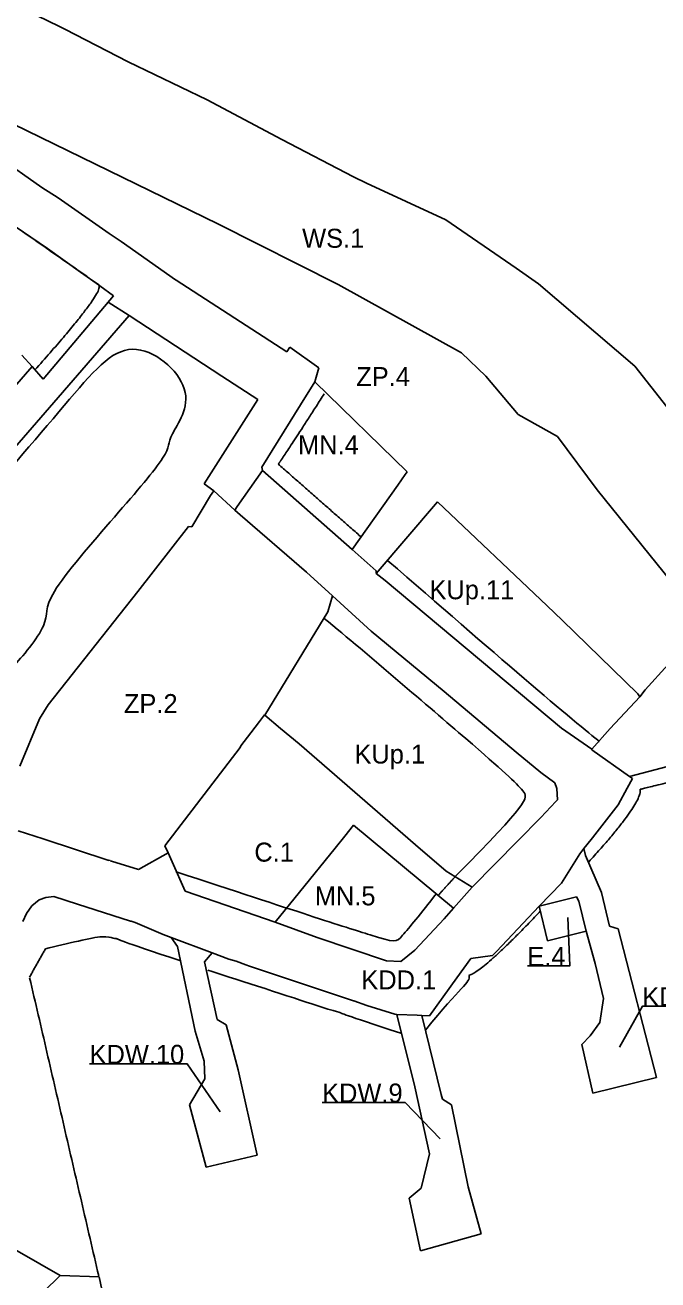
# Model space of a CAD drawing. Extents: x 7424788 to 7425732, y 5549810 to 5550591.
# Drawn here: x 7425283.7 to 7425416.8, y 5550184.4 to 5550448.5 of the extents above; entities that cross this region are included whole.
import ezdxf

# ---------------------------------------------------------------- set-up
doc = ezdxf.new("R2010")
doc.units = 0
for name, color, linetype in [('WIL_granica obszaru objętego planem', 7, 'Continuous'), ('WIL_linia rozgraniczające tereny o różnym przeznaczeniu lub różnych zasadach zagospodarowania', 7, 'Continuous'), ('WIL_linia rozgraniczające tereny o różnym przeznaczeniu lub różnych zasadach zagospodarowania_OPISY', 7, 'Continuous'), ('WIL_nieprzekraczalne linie zabudowy', 7, 'Continuous')]:
    doc.layers.add(name, color=color, linetype=linetype)

msp = doc.modelspace()

# ---------------------------------------------------------------- linework, layer by layer
at = {"layer": 'WIL_granica obszaru objętego planem'}
for p, q in [((7425283.84, 5550451.64), (7425290.93, 5550448.2)), ((7425290.93, 5550448.2), (7425292.05, 5550447.63)), ((7425292.05, 5550447.63), (7425305.36, 5550440.81)), ((7425305.36, 5550440.81), (7425321.99, 5550432.8)), ((7425321.99, 5550432.8), (7425337.74, 5550424.46)), ((7425337.74, 5550424.46), (7425352.81, 5550416.55)), ((7425352.81, 5550416.55), (7425355.56, 5550415.28)), ((7425355.56, 5550415.28), (7425372.22, 5550407.56)), ((7425372.22, 5550407.56), (7425386.99, 5550397.33)), ((7425386.99, 5550397.33), (7425391.75, 5550394.04)), ((7425391.75, 5550394.04), (7425411.96, 5550376.76)), ((7425411.96, 5550376.76), (7425426.3, 5550358.5))]:
    msp.add_line(p, q, dxfattribs=at)
at = {"layer": 'WIL_linia rozgraniczające tereny o różnym przeznaczeniu lub różnych zasadach zagospodarowania'}
for p, q in [((7425283.84, 5550451.64), (7425290.93, 5550448.2)), ((7425290.93, 5550448.2), (7425292.05, 5550447.63)), ((7425292.05, 5550447.63), (7425305.36, 5550440.81)), ((7425305.36, 5550440.81), (7425321.99, 5550432.8)), ((7425321.99, 5550432.8), (7425337.74, 5550424.46)), ((7425278.31, 5550429.04), (7425324.29, 5550406.7)), ((7425337.74, 5550424.46), (7425352.81, 5550416.55)), ((7425287.26, 5550414.34), (7425277.85, 5550420.91)), ((7425352.81, 5550416.55), (7425355.56, 5550415.28)), ((7425290.7, 5550412.16), (7425287.26, 5550414.34)), ((7425355.56, 5550415.28), (7425372.22, 5550407.56)), ((7425301.42, 5550404.68), (7425290.7, 5550412.16)), ((7425288.42, 5550401.48), (7425281.41, 5550406.3)), ((7425324.29, 5550406.7), (7425349.6, 5550393.9)), ((7425372.22, 5550407.56), (7425386.99, 5550397.33)), ((7425303.95, 5550403), (7425301.42, 5550404.68)), ((7425295.4, 5550396.55), (7425288.42, 5550401.48)), ((7425315.38, 5550394.87), (7425303.95, 5550403)), ((7425299.38, 5550393.69), (7425295.4, 5550396.55)), ((7425386.99, 5550397.33), (7425391.75, 5550394.04)), ((7425299.43, 5550393.65), (7425299.38, 5550393.69)), ((7425302.31, 5550391.51), (7425299.43, 5550393.65)), ((7425315.49, 5550394.8), (7425315.38, 5550394.87)), ((7425338.75, 5550379.76), (7425315.49, 5550394.8)), ((7425349.6, 5550393.9), (7425375.52, 5550379.54)), ((7425391.75, 5550394.04), (7425411.96, 5550376.76)), ((7425287.5, 5550374.02), (7425302.31, 5550391.51)), ((7425305.59, 5550387.37), (7425301.21, 5550390.22)), ((7425288.84, 5550368.05), (7425304.66, 5550386.33)), ((7425304.66, 5550386.33), (7425305.59, 5550387.37)), ((7425305.59, 5550387.37), (7425325.13, 5550374.65)), ((7425339.41, 5550380.73), (7425338.75, 5550379.76)), ((7425345.52, 5550376.4), (7425339.41, 5550380.73)), ((7425283, 5550379.03), (7425285.18, 5550376.64)), ((7425375.52, 5550379.54), (7425380.62, 5550374.6)), ((7425285.18, 5550376.64), (7425260.42, 5550348.39)), ((7425285.18, 5550376.64), (7425287.5, 5550374.02)), ((7425325.13, 5550374.65), (7425332.65, 5550369.75)), ((7425344.66, 5550373.45), (7425345.52, 5550376.4)), ((7425380.62, 5550374.6), (7425387.41, 5550366.58)), ((7425411.96, 5550376.76), (7425426.3, 5550358.5)), ((7425341.63, 5550368.63), (7425344.66, 5550373.45)), ((7425344.66, 5550373.45), (7425364.09, 5550354.52)), ((7425332.65, 5550369.75), (7425321.37, 5550351.99)), ((7425281.55, 5550359.6), (7425288.84, 5550368.05)), ((7425333.48, 5550355.5), (7425341.63, 5550368.63)), ((7425387.41, 5550366.58), (7425395.74, 5550361.95)), ((7425395.74, 5550361.95), (7425404.07, 5550350.68)), ((7425328.34, 5550347.21), (7425333.62, 5550354.76)), ((7425333.62, 5550354.76), (7425333.48, 5550355.5)), ((7425352.5, 5550338.18), (7425333.62, 5550354.76)), ((7425363.66, 5550353.95), (7425362.1, 5550351.69)), ((7425364.09, 5550354.52), (7425363.66, 5550353.95)), ((7425321.37, 5550351.99), (7425323.45, 5550350.51)), ((7425362.1, 5550351.69), (7425352.5, 5550338.18)), ((7425404.07, 5550350.68), (7425423.19, 5550326.93)), ((7425322.74, 5550349.49), (7425318.82, 5550342.91)), ((7425323.45, 5550350.51), (7425322.74, 5550349.49)), ((7425327.86, 5550346.44), (7425323.45, 5550350.51)), ((7425357.57, 5550333.12), (7425370.48, 5550348.19)), ((7425370.48, 5550348.19), (7425393.54, 5550326.29)), ((7425327.86, 5550346.44), (7425328.34, 5550347.21)), ((7425328.96, 5550345.48), (7425327.86, 5550346.44)), ((7425342.88, 5550333.36), (7425328.96, 5550345.48)), ((7425318.09, 5550342.99), (7425307.41, 5550329.28)), ((7425318.82, 5550342.91), (7425318.09, 5550342.99)), ((7425357.54, 5550333.65), (7425352.5, 5550338.18)), ((7425348.37, 5550328.37), (7425342.88, 5550333.36)), ((7425357.57, 5550333.12), (7425357.54, 5550333.65)), ((7425357.58, 5550333.07), (7425357.57, 5550333.12)), ((7425359.48, 5550331.6), (7425357.58, 5550333.07)), ((7425396.53, 5550300.55), (7425359.48, 5550331.6)), ((7425307.41, 5550329.28), (7425288.58, 5550305.46)), ((7425347.4, 5550325.01), (7425348.37, 5550328.37)), ((7425348.37, 5550328.37), (7425356.49, 5550320.98)), ((7425334.14, 5550303.26), (7425347.4, 5550325.01)), ((7425393.54, 5550326.29), (7425396.71, 5550323.28)), ((7425396.71, 5550323.28), (7425412.64, 5550307.77)), ((7425356.49, 5550320.98), (7425371.86, 5550308.29)), ((7425419.02, 5550313.96), (7425414.16, 5550308.65)), ((7425371.86, 5550308.29), (7425387.02, 5550295.51)), ((7425414.16, 5550308.65), (7425413.01, 5550307.15)), ((7425413.01, 5550307.15), (7425406.81, 5550300.45)), ((7425412.64, 5550307.77), (7425413.01, 5550307.15)), ((7425288.58, 5550305.46), (7425286.73, 5550302.51)), ((7425333.01, 5550301.92), (7425334.07, 5550303.32)), ((7425334.07, 5550303.32), (7425334.14, 5550303.26)), ((7425334.14, 5550303.26), (7425337.46, 5550300.5)), ((7425286.73, 5550302.51), (7425282.57, 5550292.54)), ((7425331.21, 5550299.55), (7425333.01, 5550301.92)), ((7425337.46, 5550300.5), (7425341.38, 5550297.24)), ((7425402.95, 5550296.13), (7425396.53, 5550300.55)), ((7425406.81, 5550300.45), (7425402.95, 5550296.13)), ((7425329.12, 5550296.8), (7425331.21, 5550299.55)), ((7425313.1, 5550275.8), (7425328.96, 5550296.5)), ((7425328.96, 5550296.5), (7425329.12, 5550296.8)), ((7425341.38, 5550297.24), (7425365.86, 5550275.99)), ((7425387.02, 5550295.51), (7425392.21, 5550291.24)), ((7425402.95, 5550296.13), (7425402.92, 5550296.01)), ((7425402.92, 5550296.01), (7425410.83, 5550290.4)), ((7425410.83, 5550290.4), (7425431.76, 5550295.88)), ((7425392.21, 5550291.24), (7425395.14, 5550289.05)), ((7425411.46, 5550289.96), (7425410.36, 5550287.92)), ((7425410.83, 5550290.4), (7425411.46, 5550289.96)), ((7425395.14, 5550289.05), (7425395.6, 5550287.88)), ((7425395.6, 5550287.88), (7425395.72, 5550285.49)), ((7425410.36, 5550287.92), (7425408.49, 5550284.43)), ((7425395.34, 5550285.09), (7425392.19, 5550281.76)), ((7425395.72, 5550285.49), (7425395.34, 5550285.09)), ((7425408.49, 5550284.43), (7425403.07, 5550277.5)), ((7425350.96, 5550277.84), (7425352.8, 5550280.12)), ((7425352.8, 5550280.12), (7425373.84, 5550262.67)), ((7425392.19, 5550281.76), (7425387.38, 5550276.86)), ((7425282.27, 5550278.94), (7425287.49, 5550277.24)), ((7425287.49, 5550277.24), (7425301.33, 5550272.71)), ((7425348.91, 5550275.3), (7425350.96, 5550277.84)), ((7425387.38, 5550276.86), (7425377.77, 5550267.07)), ((7425402.78, 5550277.13), (7425401.28, 5550275.21)), ((7425403.07, 5550277.5), (7425402.78, 5550277.13)), ((7425307.56, 5550270.77), (7425313.79, 5550274.34)), ((7425313.79, 5550274.34), (7425313.1, 5550275.8)), ((7425314.64, 5550272.44), (7425313.79, 5550274.34)), ((7425341.44, 5550266.03), (7425348.91, 5550275.3)), ((7425365.86, 5550275.99), (7425372.28, 5550270.42)), ((7425396.55, 5550267.91), (7425400.41, 5550274.09)), ((7425400.41, 5550274.09), (7425401.28, 5550275.21)), ((7425401.28, 5550275.21), (7425401.61, 5550273.78)), ((7425301.33, 5550272.71), (7425301.36, 5550272.8)), ((7425301.36, 5550272.8), (7425301.62, 5550272.71)), ((7425301.62, 5550272.71), (7425301.6, 5550272.62)), ((7425301.6, 5550272.62), (7425301.9, 5550272.53)), ((7425301.9, 5550272.53), (7425307.56, 5550270.77)), ((7425317.39, 5550266.24), (7425314.64, 5550272.44)), ((7425401.61, 5550273.78), (7425404.96, 5550265.94)), ((7425372.28, 5550270.42), (7425377.77, 5550267.07)), ((7425336.32, 5550259.75), (7425317.39, 5550266.24)), ((7425336.32, 5550259.75), (7425341.44, 5550266.03)), ((7425377.77, 5550267.07), (7425373.84, 5550262.67)), ((7425391.89, 5550263.11), (7425396.54, 5550267.9)), ((7425396.54, 5550267.9), (7425396.55, 5550267.91)), ((7425286.66, 5550264.41), (7425285.11, 5550263.16)), ((7425288.06, 5550264.92), (7425286.66, 5550264.41)), ((7425289.72, 5550265.09), (7425288.06, 5550264.92)), ((7425294.74, 5550263.5), (7425289.72, 5550265.09)), ((7425305.86, 5550259.95), (7425294.74, 5550263.5)), ((7425391.89, 5550263.11), (7425399.72, 5550265.03)), ((7425399.72, 5550265.03), (7425400.19, 5550264.15)), ((7425400.19, 5550264.15), (7425401.78, 5550257.83)), ((7425404.96, 5550265.94), (7425406.65, 5550258.85)), ((7425283.97, 5550261.56), (7425283.22, 5550259.84)), ((7425285.11, 5550263.16), (7425283.97, 5550261.56)), ((7425373.84, 5550262.67), (7425371.84, 5550260.44)), ((7425391.89, 5550263.11), (7425382.87, 5550253.57)), ((7425393.61, 5550255.77), (7425391.89, 5550263.11)), ((7425306, 5550259.91), (7425305.86, 5550259.95)), ((7425306.84, 5550259.64), (7425306, 5550259.91)), ((7425312.76, 5550257.14), (7425306.84, 5550259.64)), ((7425345.18, 5550256.52), (7425336.32, 5550259.75)), ((7425371.84, 5550260.44), (7425365.7, 5550253.86)), ((7425406.65, 5550258.85), (7425408.45, 5550258.32)), ((7425408.45, 5550258.32), (7425416.57, 5550227.04)), ((7425314.41, 5550256.52), (7425312.76, 5550257.14)), ((7425314.41, 5550256.52), (7425323.03, 5550253.26)), ((7425315.78, 5550254.6), (7425314.41, 5550256.52)), ((7425359.73, 5550251.59), (7425345.18, 5550256.52)), ((7425401.78, 5550257.83), (7425393.61, 5550255.77)), ((7425403.65, 5550251), (7425401.78, 5550257.83)), ((7425319.51, 5550236.75), (7425315.78, 5550254.6)), ((7425323.03, 5550253.26), (7425321.47, 5550251.38)), ((7425326.55, 5550251.93), (7425323.03, 5550253.26)), ((7425365.7, 5550253.86), (7425362.79, 5550251.43)), ((7425382.87, 5550253.57), (7425382.05, 5550252.7)), ((7425321.47, 5550251.38), (7425324.1, 5550239.21)), ((7425328.08, 5550251.49), (7425326.55, 5550251.93)), ((7425330.12, 5550250.76), (7425328.08, 5550251.49)), ((7425330.92, 5550250.48), (7425330.12, 5550250.76)), ((7425352.79, 5550243.19), (7425330.92, 5550250.48)), ((7425362.79, 5550251.43), (7425359.73, 5550251.59)), ((7425377.47, 5550252.05), (7425374.55, 5550248.01)), ((7425382.05, 5550252.7), (7425377.47, 5550252.05)), ((7425405.39, 5550243.68), (7425403.65, 5550251)), ((7425374.55, 5550248.01), (7425368.78, 5550240.03)), ((7425352.86, 5550243.17), (7425352.79, 5550243.19)), ((7425355.63, 5550242.21), (7425352.86, 5550243.17)), ((7425404.59, 5550238.62), (7425405.39, 5550243.68)), ((7425361.46, 5550240.33), (7425355.63, 5550242.21)), ((7425361.92, 5550240.31), (7425361.46, 5550240.33)), ((7425365.71, 5550225.04), (7425361.92, 5550240.31)), ((7425361.92, 5550240.31), (7425366.17, 5550240.14)), ((7425366.17, 5550240.14), (7425367.19, 5550240.1)), ((7425367.19, 5550240.1), (7425371.22, 5550223.44)), ((7425368.78, 5550240.03), (7425367.19, 5550240.1)), ((7425324.1, 5550239.21), (7425326.04, 5550238.09)), ((7425326.04, 5550238.09), (7425328.56, 5550228.63)), ((7425402.59, 5550235.82), (7425404.59, 5550238.62)), ((7425321.38, 5550230.5), (7425319.51, 5550236.75)), ((7425400.86, 5550233.96), (7425402.59, 5550235.82)), ((7425403.12, 5550223.71), (7425400.86, 5550233.96)), ((7425321.51, 5550226.77), (7425321.38, 5550230.5)), ((7425318.31, 5550221.31), (7425321.51, 5550226.77)), ((7425328.56, 5550228.63), (7425332.56, 5550210.66)), ((7425416.57, 5550227.04), (7425403.12, 5550223.71)), ((7425368.77, 5550210.93), (7425365.71, 5550225.04)), ((7425321.77, 5550208.13), (7425318.31, 5550221.31)), ((7425371.22, 5550223.44), (7425371.5, 5550222.48)), ((7425371.5, 5550222.48), (7425373.43, 5550221.31)), ((7425373.43, 5550221.31), (7425376.89, 5550204)), ((7425332.56, 5550210.66), (7425321.77, 5550208.13)), ((7425367.04, 5550203.74), (7425368.77, 5550210.93)), ((7425364.51, 5550201.61), (7425367.04, 5550203.74)), ((7425376.89, 5550204), (7425379.69, 5550194.15)), ((7425366.91, 5550190.56), (7425364.51, 5550201.61)), ((7425268.19, 5550198.41), (7425291.09, 5550185.38)), ((7425379.69, 5550194.15), (7425366.91, 5550190.56)), ((7425291.09, 5550185.38), (7425269.43, 5550164.2)), ((7425291.09, 5550185.38), (7425299.29, 5550185.06)), ((7425299.29, 5550185.06), (7425301.41, 5550175.18))]:
    msp.add_line(p, q, dxfattribs=at)
at = {"layer": 'WIL_linia rozgraniczające tereny o różnym przeznaczeniu lub różnych zasadach zagospodarowania_OPISY'}
for points in [[(7425389.37, 5550250.5), (7425398.3, 5550250.5), (7425397.86, 5550260.73)], [(7425431.84, 5550242.02), (7425413.57, 5550242.03), (7425408.76, 5550233.41)], [(7425297.27, 5550229.9), (7425317.81, 5550229.9), (7425324.77, 5550219.83)], [(7425346.19, 5550221.76), (7425363.64, 5550221.76), (7425371.04, 5550214.12)]]:
    msp.add_lwpolyline(points, dxfattribs=at)
at = {"layer": 'WIL_nieprzekraczalne linie zabudowy'}
for points, degree in [([(7425299.17, 5550393.9), (7425272.45, 5550412.55)], 1), ([(7425285.75, 5550375.94), (7425300.77, 5550392.66), (7425299.17, 5550393.9)], 2), ([(7425198.43, 5550207.48), (7425214.24, 5550223.9), (7425226.81, 5550237.4), (7425222.97, 5550241.17), (7425243.74, 5550265.11), (7425240.43, 5550268.16), (7425240.3, 5550268.42), (7425256.84, 5550287.34), (7425277.61, 5550312.54), (7425279.73, 5550311.22), (7425289.78, 5550323.65), (7425286.52, 5550326.6), (7425303.41, 5550346.01), (7425314.85, 5550359.25), (7425313.06, 5550361.03), (7425321.13, 5550371.48), (7425305.65, 5550384.84), (7425294.14, 5550370.95), (7425269.41, 5550342.11), (7425267.03, 5550339.06), (7425265.3, 5550337.01), (7425268.22, 5550334.57), (7425251.81, 5550317.24), (7425232.23, 5550295.28), (7425230.78, 5550292.96), (7425222.05, 5550283.57), (7425219.8, 5550280.13), (7425223.37, 5550276.56), (7425206.92, 5550256.89)], 3), ([(7425346.64, 5550370.91), (7425338.54, 5550358.27), (7425336.98, 5550356.11)], 2), ([(7425336.98, 5550356.11), (7425354.5, 5550340.7)], 1), ([(7425360.03, 5550335.78), (7425381.5, 5550317.22), (7425400.16, 5550300.96), (7425404.58, 5550297.77)], 3), ([(7425374.29, 5550269.4), (7425389.58, 5550285.03), (7425389.95, 5550286.43), (7425381.27, 5550294.27), (7425356.04, 5550315.85), (7425346.66, 5550323.65)], 3), ([(7425432.56, 5550292.6), (7425414.63, 5550288.01), (7425413.11, 5550287.68)], 2), ([(7425413.11, 5550287.68), (7425413.69, 5550284.95), (7425402.32, 5550272.44)], 2), ([(7425315.47, 5550270.33), (7425340.72, 5550262.01), (7425361.29, 5550255.37), (7425362.04, 5550255.47), (7425366.9, 5550261.45), (7425370.26, 5550265.75)], 3), ([(7425370.63, 5550265.38), (7425374.29, 5550269.4)], 1), ([(7425392.17, 5550262.09), (7425379.99, 5550249.25), (7425377.07, 5550248.53)], 2), ([(7425316.46, 5550251.56), (7425303.27, 5550255.95), (7425303.08, 5550256.35), (7425302.46, 5550256.22), (7425300.43, 5550256.95), (7425295.39, 5550255.88), (7425290.13, 5550254.61), (7425287.98, 5550254.09)], 3), ([(7425287.98, 5550254.09), (7425284.64, 5550248.15)], 1), ([(7425284.67, 5550248.03), (7425299.19, 5550185.28)], 1), ([(7425362.73, 5550236.33), (7425350.25, 5550240.43), (7425350.17, 5550240.71), (7425349.7, 5550240.61), (7425326.71, 5550248.22), (7425322.12, 5550249.6)], 3), ([(7425377.12, 5550248.52), (7425377.44, 5550246.93), (7425375.41, 5550246.34), (7425367.98, 5550237)], 3)]:
    msp.add_open_spline(points, degree=degree, dxfattribs=at)

# ---------------------------------------------------------------- texts
at = {"layer": 'WIL_linia rozgraniczające tereny o różnym przeznaczeniu lub różnych zasadach zagospodarowania_OPISY'}
for s, p in [('WS.1', (7425341.99, 5550401.65)), ('ZP.4', (7425353.37, 5550372.54)), ('MN.4', (7425341.12, 5550358.18)), ('KUp.11', (7425368.78, 5550327.68)), ('ZP.2', (7425304.49, 5550303.72)), ('KUp.1', (7425353, 5550293.1)), ('C.1', (7425331.94, 5550272.46)), ('MN.5', (7425344.65, 5550263.26)), ('E.4', (7425389.37, 5550250.5)), ('KDD.1', (7425354.45, 5550245.57)), ('KDW.8', (7425413.57, 5550242.03)), ('KDW.10', (7425297.27, 5550229.9)), ('KDW.9', (7425346.19, 5550221.76))]:
    msp.add_text(s, height=4, dxfattribs=at).set_placement(p)

doc.saveas('drawing.dxf')
